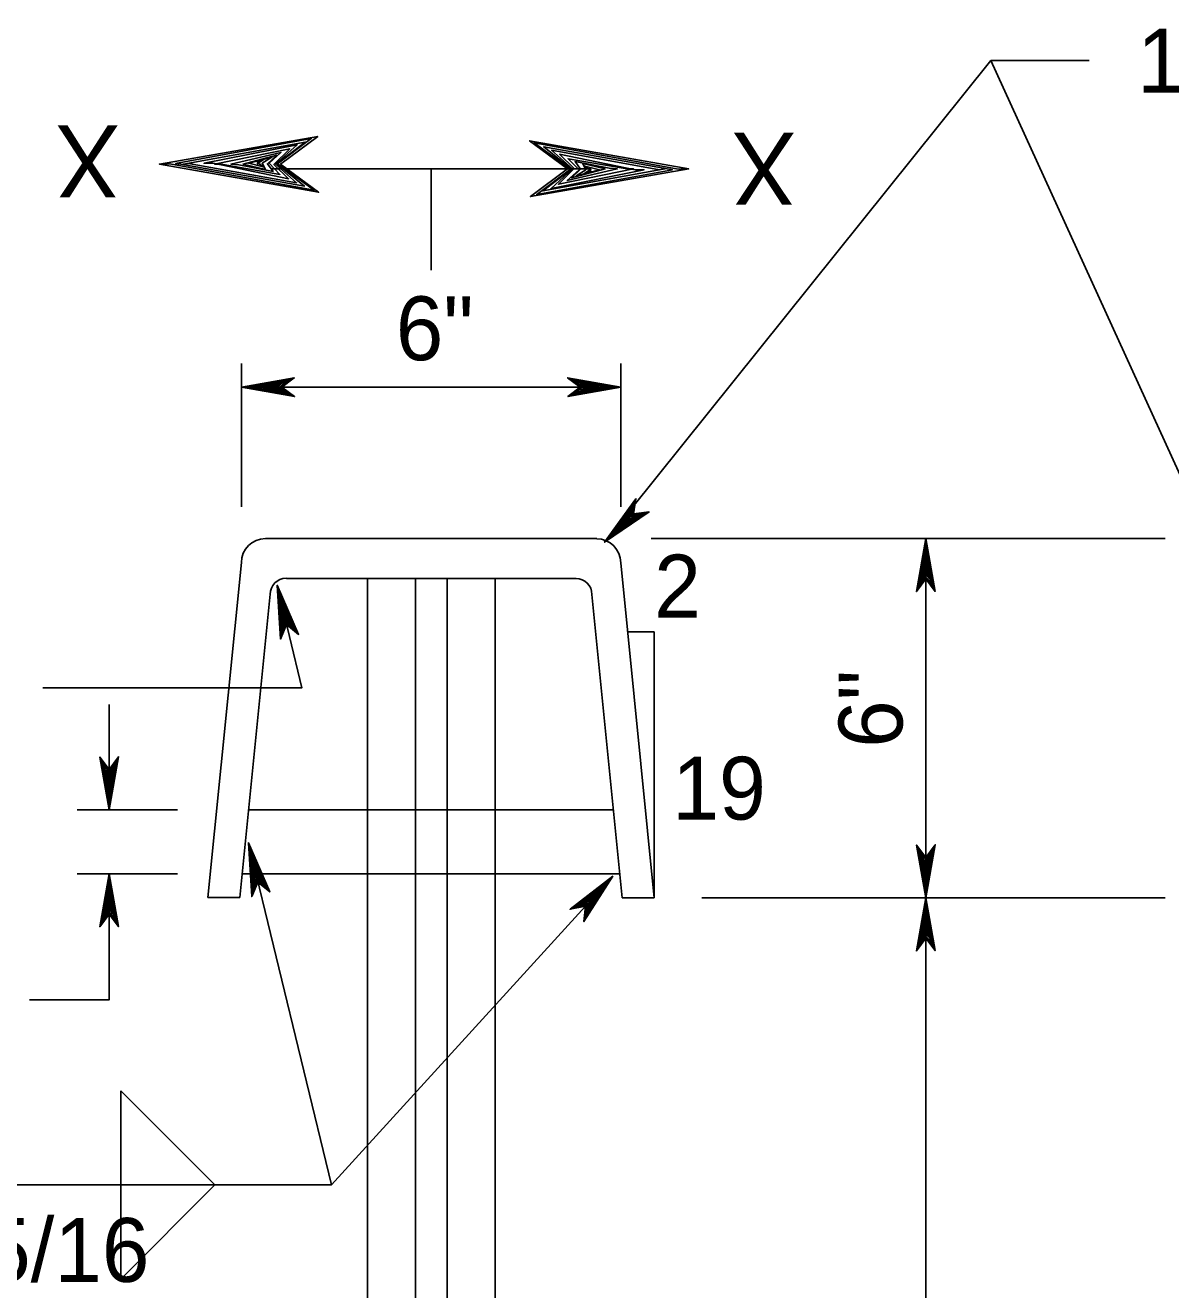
# Model space of a CAD drawing. Extents: x 499883 to 500983, y 499104 to 499764.
# Drawn here: x 500568.6 to 500640.4, y 499221.1 to 499300.2 of the extents above; entities that cross this region are included whole.
import ezdxf

# ---------------------------------------------------------------- set-up
doc = ezdxf.new("R2010")
doc.units = 0
for name, color, linetype in [('2', 7, 'Continuous'), ('24', 7, 'Continuous'), ('5', 7, 'Continuous')]:
    doc.layers.add(name, color=color, linetype=linetype)

msp = doc.modelspace()

# ---------------------------------------------------------------- linework, layer by layer
at = {"layer": '2'}
for p, q in [((500594.055, 499291.227), (500594.055, 499284.897)), ((500590.058, 499265.584), (500590.058, 499251.071)), ((500593.056, 499265.584), (500593.056, 499170.656)), ((500595.054, 499265.584), (500595.054, 499170.656)), ((500598.052, 499265.584), (500598.052, 499251.071)), ((500590.058, 499247.084), (500590.058, 499170.656)), ((500598.052, 499247.044), (500598.052, 499170.656))]:
    msp.add_line(p, q, dxfattribs=at)
at = {"layer": '24'}
for points in [[(500573.879, 499251.095), (500574.467, 499254.419), (500573.879, 499253.625), (500573.301, 499254.402), (500573.879, 499251.095), (500573.873, 499251.316), (500574.423, 499254.326), (500573.872, 499253.563), (500573.346, 499254.268), (500573.863, 499251.435), (500573.879, 499251.545), (500574.337, 499254.124), (500573.872, 499253.545), (500573.421, 499254.14), (500573.879, 499251.596), (500573.863, 499251.707), (500574.269, 499253.96), (500573.879, 499253.522), (500573.474, 499253.969), (500573.863, 499252.028), (500573.863, 499252.215), (500574.186, 499253.793), (500573.889, 499253.486), (500573.558, 499253.817), (500573.879, 499252.249), (500573.889, 499252.426), (500574.092, 499253.613), (500573.862, 499253.384), (500573.635, 499253.632), (500573.879, 499252.589), (500573.896, 499252.757), (500574.032, 499253.469), (500573.872, 499253.352), (500573.694, 499253.546), (500573.879, 499252.843), (500573.99, 499253.308), (500573.863, 499253.241), (500573.735, 499253.445), (500573.862, 499252.96), (500573.938, 499253.265), (500573.838, 499253.138), (500573.778, 499253.284), (500573.872, 499253.138), (500573.889, 499253.215)], [(500573.879, 499251.095), (500574.467, 499254.419), (500573.879, 499253.625), (500573.301, 499254.402), (500573.879, 499251.095), (500573.873, 499251.316), (500574.423, 499254.326), (500573.872, 499253.563), (500573.346, 499254.268), (500573.863, 499251.435), (500573.879, 499251.545), (500574.337, 499254.124), (500573.872, 499253.545), (500573.421, 499254.14), (500573.879, 499251.596), (500573.863, 499251.707), (500574.269, 499253.96), (500573.879, 499253.522), (500573.474, 499253.969), (500573.863, 499252.028), (500573.863, 499252.215), (500574.186, 499253.793), (500573.889, 499253.486), (500573.558, 499253.817), (500573.879, 499252.249), (500573.889, 499252.426), (500574.092, 499253.613), (500573.862, 499253.384), (500573.635, 499253.632), (500573.879, 499252.589), (500573.896, 499252.757), (500574.032, 499253.469), (500573.872, 499253.352), (500573.694, 499253.546), (500573.879, 499252.843), (500573.99, 499253.308), (500573.863, 499253.241), (500573.735, 499253.445), (500573.862, 499252.96), (500573.938, 499253.265), (500573.838, 499253.138), (500573.778, 499253.284), (500573.872, 499253.138), (500573.889, 499253.215)], [(500582.599, 499249.033), (500582.812, 499245.664), (500583.196, 499246.574), (500583.941, 499245.956), (500582.599, 499249.033), (500582.657, 499248.82), (500582.832, 499245.765), (500583.188, 499246.636), (500583.865, 499246.076), (500582.695, 499248.707), (500582.705, 499248.595), (500582.868, 499245.981), (500583.183, 499246.653), (500583.763, 499246.182), (500582.717, 499248.546), (500582.759, 499248.442), (500582.895, 499246.156), (500583.171, 499246.674), (500583.671, 499246.335), (500582.835, 499248.13), (500582.879, 499247.948), (500582.938, 499246.338), (500583.154, 499246.707), (500583.553, 499246.463), (500582.871, 499247.912), (500582.903, 499247.737), (500582.985, 499246.536), (500583.155, 499246.812), (500583.435, 499246.625), (500582.951, 499247.581), (500582.974, 499247.414), (500583.01, 499246.689), (500583.138, 499246.841), (500583.357, 499246.695), (500583.011, 499247.334), (500583.013, 499246.856), (500583.121, 499246.951), (500583.293, 499246.783), (500583.056, 499247.224), (500583.053, 499246.91), (500583.12, 499247.058), (500583.213, 499246.929), (500583.088, 499247.049), (500583.09, 499246.971)], [(500582.599, 499249.033), (500582.812, 499245.664), (500583.196, 499246.574), (500583.941, 499245.956), (500582.599, 499249.033), (500582.657, 499248.82), (500582.832, 499245.765), (500583.188, 499246.636), (500583.865, 499246.076), (500582.695, 499248.707), (500582.705, 499248.595), (500582.868, 499245.981), (500583.183, 499246.653), (500583.763, 499246.182), (500582.717, 499248.546), (500582.759, 499248.442), (500582.895, 499246.156), (500583.171, 499246.674), (500583.671, 499246.335), (500582.835, 499248.13), (500582.879, 499247.948), (500582.938, 499246.338), (500583.154, 499246.707), (500583.553, 499246.463), (500582.871, 499247.912), (500582.903, 499247.737), (500582.985, 499246.536), (500583.155, 499246.812), (500583.435, 499246.625), (500582.951, 499247.581), (500582.974, 499247.414), (500583.01, 499246.689), (500583.138, 499246.841), (500583.357, 499246.695), (500583.011, 499247.334), (500583.013, 499246.856), (500583.121, 499246.951), (500583.293, 499246.783), (500583.056, 499247.224), (500583.053, 499246.91), (500583.12, 499247.058), (500583.213, 499246.929), (500583.088, 499247.049), (500583.09, 499246.971)], [(500573.879, 499247.098), (500573.292, 499243.774), (500573.879, 499244.568), (500574.457, 499243.791), (500573.879, 499247.098), (500573.885, 499246.877), (500573.335, 499243.867), (500573.886, 499244.63), (500574.412, 499243.926), (500573.895, 499246.758), (500573.879, 499246.647), (500573.421, 499244.069), (500573.886, 499244.647), (500574.337, 499244.053), (500573.879, 499246.597), (500573.895, 499246.486), (500573.489, 499244.232), (500573.879, 499244.671), (500574.285, 499244.223), (500573.896, 499246.165), (500573.895, 499245.978), (500573.572, 499244.4), (500573.87, 499244.707), (500574.2, 499244.376), (500573.879, 499245.944), (500573.869, 499245.767), (500573.666, 499244.58), (500573.896, 499244.809), (500574.123, 499244.561), (500573.879, 499245.604), (500573.863, 499245.437), (500573.726, 499244.724), (500573.886, 499244.841), (500574.064, 499244.647), (500573.879, 499245.349), (500573.768, 499244.885), (500573.895, 499244.952), (500574.023, 499244.748), (500573.896, 499245.232), (500573.82, 499244.928), (500573.92, 499245.055), (500573.98, 499244.909), (500573.886, 499245.055), (500573.87, 499244.978)], [(500573.879, 499247.098), (500573.292, 499243.774), (500573.879, 499244.568), (500574.457, 499243.791), (500573.879, 499247.098), (500573.885, 499246.877), (500573.335, 499243.867), (500573.886, 499244.63), (500574.412, 499243.926), (500573.895, 499246.758), (500573.879, 499246.647), (500573.421, 499244.069), (500573.886, 499244.647), (500574.337, 499244.053), (500573.879, 499246.597), (500573.895, 499246.486), (500573.489, 499244.232), (500573.879, 499244.671), (500574.285, 499244.223), (500573.896, 499246.165), (500573.895, 499245.978), (500573.572, 499244.4), (500573.87, 499244.707), (500574.2, 499244.376), (500573.879, 499245.944), (500573.869, 499245.767), (500573.666, 499244.58), (500573.896, 499244.809), (500574.123, 499244.561), (500573.879, 499245.604), (500573.863, 499245.437), (500573.726, 499244.724), (500573.886, 499244.841), (500574.064, 499244.647), (500573.879, 499245.349), (500573.768, 499244.885), (500573.895, 499244.952), (500574.023, 499244.748), (500573.896, 499245.232), (500573.82, 499244.928), (500573.92, 499245.055), (500573.98, 499244.909), (500573.886, 499245.055), (500573.87, 499244.978)], [(500587.802, 499227.609), (500605.415, 499246.934)], [(500605.415, 499246.934), (500602.742, 499244.873), (500603.711, 499245.064), (500603.615, 499244.1), (500605.415, 499246.934), (500605.271, 499246.766), (500602.837, 499244.912), (500603.758, 499245.105), (500603.672, 499244.23), (500605.198, 499246.671), (500605.112, 499246.601), (500603.036, 499245.004), (500603.769, 499245.118), (500603.702, 499244.375), (500605.078, 499246.563), (500605.015, 499246.471), (500603.196, 499245.079), (500603.78, 499245.14), (500603.778, 499244.536), (500604.8, 499246.233), (500604.673, 499246.095), (500603.371, 499245.146), (500603.798, 499245.173), (500603.819, 499244.706), (500604.638, 499246.081), (500604.511, 499245.957), (500603.561, 499245.217), (500603.885, 499245.23), (500603.887, 499244.894), (500604.409, 499245.829), (500604.283, 499245.717), (500603.703, 499245.282), (500603.9, 499245.261), (500603.901, 499244.998), (500604.237, 499245.642), (500603.843, 499245.373), (500603.982, 499245.336), (500603.938, 499245.1), (500604.171, 499245.543), (500603.909, 499245.37), (500604.07, 499245.396), (500604.015, 499245.248), (500604.044, 499245.419), (500603.98, 499245.374)]]:
    msp.add_lwpolyline(points, dxfattribs=at)
at = {"layer": '5'}
for p, q in [((500629.104, 499298.008), (500642.582, 499268.456)), ((500594.055, 499291.227), (500584.062, 499291.227)), ((500604.047, 499291.227), (500594.055, 499291.227)), ((500582.163, 499270.076), (500582.163, 499279.043)), ((500605.917, 499270.076), (500605.917, 499279.043)), ((500582.163, 499277.561), (500605.917, 499277.561)), ((500583.662, 499268.082), (500604.418, 499268.082)), ((500607.83, 499268.082), (500640.013, 499268.082)), ((500625.024, 499268.082), (500625.024, 499245.588)), ((500580.065, 499245.599), (500582.163, 499266.579)), ((500608.015, 499245.588), (500605.917, 499266.569)), ((500584.991, 499265.584), (500603.118, 499265.584)), ((500582.064, 499245.599), (500583.964, 499264.595)), ((500606.017, 499245.588), (500604.117, 499264.585)), ((500608.015, 499262.239), (500606.411, 499262.239)), ((500608.015, 499245.588), (500608.015, 499262.239)), ((500573.879, 499257.701), (500573.879, 499251.095)), ((500573.879, 499257.701), (500573.879, 499251.095)), ((500578.156, 499251.095), (500571.881, 499251.095)), ((500578.156, 499251.095), (500571.881, 499251.095)), ((500582.608, 499251.095), (500605.434, 499251.095)), ((500590.058, 499251.071), (500590.058, 499247.084)), ((500598.052, 499251.071), (500598.052, 499247.044)), ((500587.802, 499227.609), (500582.599, 499249.033)), ((500578.156, 499247.098), (500571.881, 499247.098)), ((500578.156, 499247.098), (500571.881, 499247.098)), ((500578.156, 499247.098), (500571.881, 499247.098)), ((500573.879, 499247.098), (500573.879, 499242.012)), ((500582.209, 499247.098), (500605.827, 499247.098)), ((500582.064, 499245.599), (500580.065, 499245.599)), ((500606.017, 499245.588), (500608.015, 499245.588)), ((500610.992, 499245.588), (500640.013, 499245.588)), ((500625.024, 499245.588), (500625.024, 499170.656)), ((500574.615, 499233.5), (500580.505, 499227.609)), ((500574.615, 499233.5), (500574.615, 499221.718)), ((500564.061, 499227.609), (500580.505, 499227.609)), ((500580.505, 499227.609), (500574.615, 499221.718)), ((500580.505, 499227.609), (500587.802, 499227.609))]:
    msp.add_line(p, q, dxfattribs=at)
for points in [[(500635.26, 499298.008), (500629.104, 499298.008), (500604.904, 499267.853)], [(500577.022, 499291.528), (500586.994, 499289.766), (500584.612, 499291.528), (500586.942, 499293.263), (500577.022, 499291.528), (500577.684, 499291.547), (500586.714, 499289.896), (500584.425, 499291.55), (500586.539, 499293.126), (500578.042, 499291.577), (500578.374, 499291.528), (500586.109, 499290.153), (500584.373, 499291.549), (500586.159, 499292.902), (500578.526, 499291.528), (500578.857, 499291.577), (500585.619, 499290.357), (500584.304, 499291.528), (500585.646, 499292.744), (500579.82, 499291.579), (500580.383, 499291.578), (500585.117, 499290.608), (500584.196, 499291.5), (500585.188, 499292.492), (500580.483, 499291.528), (500581.016, 499291.498), (500584.576, 499290.888), (500583.891, 499291.579), (500584.633, 499292.262), (500581.505, 499291.528), (500582.007, 499291.478), (500584.145, 499291.069), (500583.793, 499291.55), (500584.375, 499292.082), (500582.267, 499291.527), (500583.661, 499291.197), (500583.46, 499291.578), (500584.072, 499291.96), (500582.619, 499291.579), (500583.533, 499291.349), (500583.15, 499291.651), (500583.59, 499291.831), (500583.152, 499291.55), (500583.381, 499291.5)], [(500610.179, 499291.227), (500600.207, 499292.99), (500602.589, 499291.227), (500600.259, 499289.492), (500610.179, 499291.227), (500609.516, 499291.208), (500600.487, 499292.859), (500602.776, 499291.205), (500600.662, 499289.628), (500609.159, 499291.178), (500608.827, 499291.227), (500601.092, 499292.601), (500602.828, 499291.207), (500601.042, 499289.853), (500608.676, 499291.227), (500608.344, 499291.178), (500601.582, 499292.398), (500602.897, 499291.227), (500601.555, 499290.011), (500607.381, 499291.177), (500606.818, 499291.177), (500602.084, 499292.146), (500603.005, 499291.255), (500602.013, 499290.263), (500606.718, 499291.227), (500606.185, 499291.257), (500602.625, 499291.867), (500603.31, 499291.176), (500602.568, 499290.494), (500605.696, 499291.227), (500605.194, 499291.277), (500603.057, 499291.686), (500603.408, 499291.205), (500602.826, 499290.673), (500604.934, 499291.228), (500603.54, 499291.559), (500603.741, 499291.177), (500603.129, 499290.795), (500604.583, 499291.176), (500603.668, 499291.405), (500604.051, 499291.104), (500603.612, 499290.924), (500604.049, 499291.205), (500603.82, 499291.255)], [(500582.163, 499277.561), (500585.487, 499276.973), (500584.693, 499277.561), (500585.47, 499278.139), (500582.163, 499277.561), (500582.384, 499277.567), (500585.394, 499277.016), (500584.631, 499277.567), (500585.336, 499278.093), (500582.503, 499277.577), (500582.614, 499277.561), (500585.192, 499277.102), (500584.614, 499277.567), (500585.209, 499278.018), (500582.664, 499277.561), (500582.775, 499277.577), (500585.029, 499277.17), (500584.59, 499277.561), (500585.038, 499277.965), (500583.096, 499277.577), (500583.283, 499277.577), (500584.862, 499277.254), (500584.555, 499277.551), (500584.885, 499277.882), (500583.317, 499277.561), (500583.495, 499277.55), (500584.682, 499277.347), (500584.453, 499277.577), (500584.7, 499277.805), (500583.658, 499277.561), (500583.825, 499277.543), (500584.538, 499277.407), (500584.42, 499277.567), (500584.615, 499277.745), (500583.912, 499277.56), (500584.377, 499277.45), (500584.31, 499277.577), (500584.513, 499277.705), (500584.029, 499277.577), (500584.334, 499277.501), (500584.206, 499277.601), (500584.353, 499277.661), (500584.206, 499277.567), (500584.283, 499277.551)], [(500605.917, 499277.561), (500602.593, 499278.148), (500603.387, 499277.561), (500602.611, 499276.982), (500605.917, 499277.561), (500605.696, 499277.554), (500602.686, 499278.104), (500603.45, 499277.553), (500602.745, 499277.028), (500605.578, 499277.544), (500605.466, 499277.561), (500602.888, 499278.019), (500603.467, 499277.554), (500602.872, 499277.103), (500605.416, 499277.561), (500605.306, 499277.544), (500603.052, 499277.951), (500603.49, 499277.561), (500603.043, 499277.155), (500604.985, 499277.543), (500604.797, 499277.544), (500603.219, 499277.867), (500603.526, 499277.57), (500603.195, 499277.239), (500604.764, 499277.561), (500604.586, 499277.571), (500603.399, 499277.774), (500603.627, 499277.543), (500603.38, 499277.316), (500604.423, 499277.561), (500604.255, 499277.577), (500603.543, 499277.713), (500603.661, 499277.553), (500603.466, 499277.376), (500604.169, 499277.561), (500603.704, 499277.671), (500603.771, 499277.544), (500603.567, 499277.417), (500604.052, 499277.543), (500603.747, 499277.62), (500603.875, 499277.52), (500603.728, 499277.459), (500603.874, 499277.553), (500603.798, 499277.57)], [(500604.904, 499267.853), (500607.692, 499269.756), (500606.713, 499269.622), (500606.864, 499270.578), (500604.904, 499267.853), (500605.058, 499268.012), (500607.594, 499269.722), (500606.664, 499269.583), (500606.8, 499270.451), (500605.136, 499268.102), (500605.226, 499268.168), (500607.391, 499269.643), (500606.651, 499269.571), (500606.761, 499270.309), (500605.263, 499268.203), (500605.33, 499268.292), (500607.226, 499269.577), (500606.64, 499269.549), (500606.676, 499270.152), (500605.559, 499268.517), (500605.693, 499268.648), (500607.048, 499269.52), (500606.62, 499269.518), (500606.626, 499269.985), (500605.729, 499268.659), (500605.863, 499268.776), (500606.853, 499269.46), (500606.529, 499269.465), (500606.547, 499269.801), (500605.972, 499268.897), (500606.104, 499269.002), (500606.708, 499269.403), (500606.513, 499269.436), (500606.527, 499269.699), (500606.155, 499269.075), (500606.564, 499269.321), (500606.427, 499269.365), (500606.484, 499269.599), (500606.226, 499269.169), (500606.497, 499269.327), (500606.336, 499269.31), (500606.399, 499269.455), (500606.36, 499269.286), (500606.426, 499269.328)], [(500625.024, 499268.082), (500624.436, 499264.758), (500625.024, 499265.552), (500625.602, 499264.775), (500625.024, 499268.082), (500625.03, 499267.861), (500624.48, 499264.851), (500625.031, 499265.614), (500625.557, 499264.91), (500625.04, 499267.742), (500625.024, 499267.631), (500624.566, 499265.053), (500625.031, 499265.632), (500625.482, 499265.036), (500625.024, 499267.581), (500625.04, 499267.471), (500624.634, 499265.216), (500625.024, 499265.655), (500625.429, 499265.207), (500625.041, 499267.149), (500625.04, 499266.962), (500624.717, 499265.384), (500625.015, 499265.691), (500625.345, 499265.36), (500625.024, 499266.929), (500625.014, 499266.751), (500624.81, 499265.564), (500625.041, 499265.792), (500625.268, 499265.545), (500625.024, 499266.587), (500625.007, 499266.42), (500624.871, 499265.708), (500625.031, 499265.825), (500625.208, 499265.631), (500625.023, 499266.334), (500624.913, 499265.869), (500625.04, 499265.936), (500625.168, 499265.732), (500625.041, 499266.217), (500624.964, 499265.912), (500625.065, 499266.04), (500625.125, 499265.893), (500625.031, 499266.039), (500625.015, 499265.962)], [(500569.716, 499258.729), (500585.944, 499258.729), (500584.407, 499265.159)], [(500584.407, 499265.159), (500584.609, 499261.79), (500584.995, 499262.699), (500585.739, 499262.077), (500584.407, 499265.159), (500584.464, 499264.946), (500584.629, 499261.89), (500584.988, 499262.761), (500585.663, 499262.197), (500584.502, 499264.832), (500584.512, 499264.721), (500584.666, 499262.106), (500584.984, 499262.777), (500585.561, 499262.304), (500584.523, 499264.671), (500584.565, 499264.568), (500584.694, 499262.281), (500584.972, 499262.798), (500585.47, 499262.458), (500584.641, 499264.256), (500584.684, 499264.073), (500584.737, 499262.463), (500584.954, 499262.831), (500585.353, 499262.586), (500584.676, 499264.037), (500584.706, 499263.862), (500584.785, 499262.66), (500584.956, 499262.936), (500585.235, 499262.749), (500584.755, 499263.706), (500584.777, 499263.539), (500584.81, 499262.814), (500584.939, 499262.965), (500585.157, 499262.818), (500584.813, 499263.459), (500584.814, 499262.981), (500584.922, 499263.075), (500585.094, 499262.907), (500584.857, 499263.349), (500584.854, 499263.034), (500584.922, 499263.182), (500585.015, 499263.053), (500584.889, 499263.173), (500584.891, 499263.095)], [(500625.024, 499245.588), (500625.611, 499248.912), (500625.024, 499248.118), (500624.446, 499248.895), (500625.024, 499245.588), (500625.017, 499245.809), (500625.568, 499248.819), (500625.017, 499248.056), (500624.491, 499248.761), (500625.007, 499245.929), (500625.024, 499246.039), (500625.482, 499248.618), (500625.017, 499248.039), (500624.566, 499248.634), (500625.024, 499246.089), (500625.007, 499246.2), (500625.414, 499248.454), (500625.024, 499248.016), (500624.619, 499248.463), (500625.007, 499246.521), (500625.007, 499246.709), (500625.33, 499248.287), (500625.033, 499247.98), (500624.703, 499248.311), (500625.024, 499246.742), (500625.034, 499246.919), (500625.237, 499248.106), (500625.007, 499247.878), (500624.779, 499248.125), (500625.024, 499247.083), (500625.041, 499247.25), (500625.177, 499247.963), (500625.017, 499247.845), (500624.839, 499248.04), (500625.024, 499247.337), (500625.135, 499247.801), (500625.007, 499247.734), (500624.88, 499247.938), (500625.007, 499247.454), (500625.083, 499247.759), (500624.983, 499247.631), (500624.923, 499247.778), (500625.017, 499247.632), (500625.033, 499247.708)], [(500573.879, 499247.098), (500573.879, 499239.208), (500568.883, 499239.208)], [(500625.024, 499245.588), (500624.436, 499242.265), (500625.024, 499243.059), (500625.602, 499242.282), (500625.024, 499245.588), (500625.03, 499245.368), (500624.48, 499242.358), (500625.031, 499243.121), (500625.557, 499242.416), (500625.04, 499245.249), (500625.024, 499245.138), (500624.566, 499242.559), (500625.031, 499243.138), (500625.482, 499242.543), (500625.024, 499245.087), (500625.04, 499244.977), (500624.634, 499242.723), (500625.024, 499243.161), (500625.429, 499242.714), (500625.041, 499244.656), (500625.04, 499244.468), (500624.717, 499242.89), (500625.015, 499243.197), (500625.345, 499242.866), (500625.024, 499244.435), (500625.014, 499244.257), (500624.81, 499243.071), (500625.041, 499243.299), (500625.268, 499243.052), (500625.024, 499244.094), (500625.007, 499243.927), (500624.871, 499243.214), (500625.031, 499243.332), (500625.208, 499243.137), (500625.023, 499243.84), (500624.913, 499243.375), (500625.04, 499243.442), (500625.168, 499243.238), (500625.041, 499243.723), (500624.964, 499243.418), (500625.065, 499243.546), (500625.125, 499243.399), (500625.031, 499243.545), (500625.015, 499243.469)]]:
    msp.add_lwpolyline(points, dxfattribs=at)
for centre, radius, start, end in [((500583.662, 499266.579), 1.499, 90, 180), ((500604.418, 499266.569), 1.499, 0, 90), ((500584.963, 499264.595), 0.999, 90, 180), ((500603.118, 499264.585), 0.999, 0, 90)]:
    msp.add_arc(centre, radius, start, end, dxfattribs=at)

# ---------------------------------------------------------------- texts
for s, height, p in [('1/2" PLATE', 4, (500638.26, 499296.008)), ('6"', 4, (500591.831, 499279.248)), ('2', 3.937, (500608.013, 499263.138)), ('19', 3.937, (500609.149, 499250.484)), ('5/16', 4, (500565.986, 499221.539))]:
    msp.add_text(s, height=height, dxfattribs=at).set_placement(p)
for s, height, rotation, p in [('X', 4.5, 180, (500574.543, 499293.95)), ('X', 4.5, 180, (500616.894, 499293.498)), ('6"', 4, 90, (500623.564, 499254.982))]:
    msp.add_text(s, height=height, rotation=rotation, dxfattribs=at).set_placement(p)

doc.saveas('drawing.dxf')
